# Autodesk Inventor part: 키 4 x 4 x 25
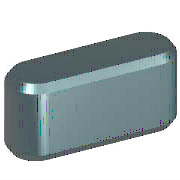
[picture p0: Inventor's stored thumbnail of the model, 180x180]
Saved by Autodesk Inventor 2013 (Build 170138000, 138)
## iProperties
IsCustomPart: 1
Created: 2012-02
Part Number: 키 4 x 4 x 25
Material: 강철, 연강
Description: 키 및 해당 키홈
Document SubType Name: Modeling
Standard: KS B 1311
Designer: mduedu
Standards Organization: KS
Language: ko-KR
Size Designation: 4 x 4 x 25
Categories: <MemberInstance><Categories><Category DisplayName="샤프트 부품" InternalName="7f7aeb1f-a693-4053-b835-cee3144e0d98" Mnemonic="SHFT"><Category DisplayName="키" Interna
Density: 7.86 g/cm^3
Mass: 3.0095 g
Surface Area: 3.95253 cm^2
Volume: 0.382888 cm^3
Author: mduedu
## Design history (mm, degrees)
workplane "Work Plane1"
workplane "Work Plane2"
sketch "스케치1"
  geometry: L1 (2, 2)-(23, 2); L2 (23, -2)-(2, -2); L3 (0, 9.4)-(0, -7.4) reference; L4 (-5, 0)-(30, 0) reference; L5 (25, 0)-(25, 7); A1 r 2 centre (2, 0) between (2, 2) and (2, -2); A2 r 2 centre (23, 0) between (23, -2) and (23, 2)
  constraints: 6 end point, 5 point on circle, 4 tangent, 3 point on line, 2 centre point, 1 horizontal, 1 parallel, 1 perpendicular
  dimensions: "d0" = 2 radius of A1 (= 0.5 x PB); "d13" = 2 radius of A2 (= 0.5 x PB); "d14" = 25 distance between parallel lines of L5 L3 (= NLG)
extrude "본체1" new body sketch "스케치1" taper "d3" = 0 deg; stored distance "d4" = 10
workplane "Work Plane3"
body "Solid1"
chamfer "모따기1" distance "d8" = 0.25 (= PHH); stored, may be unused: second distance "d9" = 0.25 (= PHH), angle "d15" = 45 deg
other parameters: "d1" = -2.5 (= -PNT), "d2" = 1.5 (= PH - PNT), "NLG" = 25 [user parameter; used in 3 equation terms], "PB" = 4 [user parameter; used in 2 equation terms], "PNT" = 2.5 [user parameter; used in 2 equation terms], "PH" = 4 [user parameter; used in 1 equation term], "PHH" = 0.25 [user parameter; used in 2 equation terms], "d10" = 0, "d16" = 0, "d17" = 0, "d18" = 0, "PLB2" = 25 (= NLG) [user parameter], "WDMAX" = 12 [user parameter], "PLB1" = 25 (= NLG) [user parameter], "RR" = 0.08 [user parameter], "PUEB" = 1.8 [user parameter]
